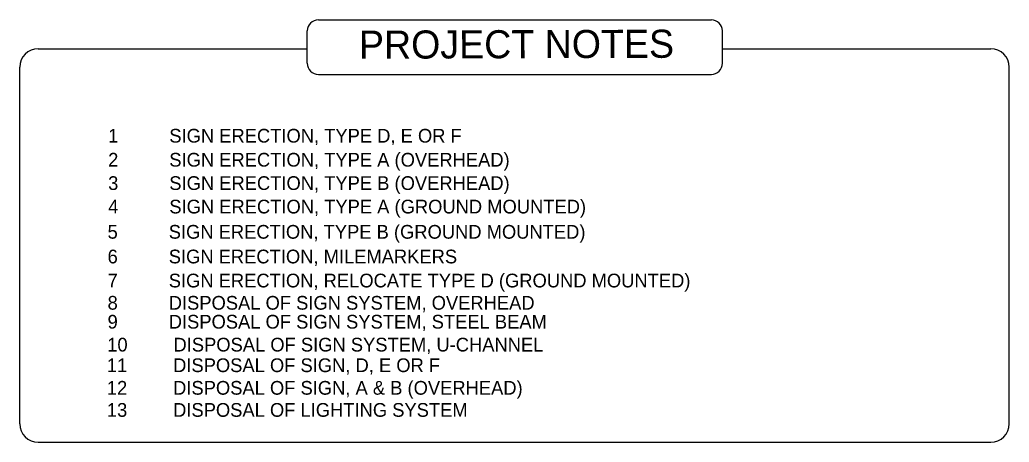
# Model space of a CAD drawing. Extents: x 49862 to 50351, y 49646 to 49855.
import ezdxf

# ---------------------------------------------------------------- set-up
doc = ezdxf.new("R2010")
doc.units = 0
doc.layers.add('Default', color=7, linetype='Continuous')
doc.layers.add('Sheet Title CELL', color=7, linetype='Continuous')

msp = doc.modelspace()

# ---------------------------------------------------------------- linework, layer by layer
at = {"layer": 'Sheet Title CELL'}
for p, q in [((50004.11, 49833.44), (50004.11, 49849.46)), ((50209.04, 49833.44), (50209.04, 49849.46)), ((49871.27, 49840.66), (50004.11, 49840.66)), ((50209.04, 49840.66), (50341.55, 49840.66)), ((49862.18, 49655.56), (49862.18, 49831.57)), ((50350.64, 49655.56), (50350.64, 49831.57)), ((49871.27, 49646.48), (50341.55, 49646.48))]:
    msp.add_line(p, q, dxfattribs=at)
for points in [[(50009.57, 49854.92), (50203.59, 49854.92)], [(50009.57, 49827.99), (50203.59, 49827.99)]]:
    msp.add_lwpolyline(points, dxfattribs=at)
for centre, radius, start, end in [((50009.57, 49849.46), 5.45, 90, 180), ((50203.59, 49849.46), 5.45, 0, 90), ((49871.27, 49831.57), 9.09, 90, 180), ((50341.55, 49831.57), 9.09, 0, 90), ((50009.57, 49833.44), 5.45, 180, 270), ((50203.59, 49833.44), 5.45, 270, 0), ((49871.27, 49655.56), 9.09, 180, 270), ((50341.55, 49655.56), 9.09, 270, 0)]:
    msp.add_arc(centre, radius, start, end, dxfattribs=at)

# ---------------------------------------------------------------- texts
at = {"layer": 'Default'}
msp.add_text('PROJECT NOTES', height=13.8661, rotation=0.1822, dxfattribs=at).set_placement((50029.63, 49835.69))
for s, p in [('1          SIGN ERECTION, TYPE D, E OR F', (49905.8, 49794.32)), ('2          SIGN ERECTION, TYPE A (OVERHEAD)', (49905.8, 49782.47)), ('3          SIGN ERECTION, TYPE B (OVERHEAD)', (49905.8, 49770.95)), ('4          SIGN ERECTION, TYPE A (GROUND MOUNTED)', (49905.8, 49759.35)), ('5          SIGN ERECTION, TYPE B (GROUND MOUNTED)', (49905.52, 49746.9)), ('6          SIGN ERECTION, MILEMARKERS', (49905.52, 49734.72)), ('7          SIGN ERECTION, RELOCATE TYPE D (GROUND MOUNTED)', (49905.52, 49722.86)), ('8          DISPOSAL OF SIGN SYSTEM, OVERHEAD', (49905.52, 49711.87)), ('9          DISPOSAL OF SIGN SYSTEM, STEEL BEAM', (49905.52, 49702.54)), ('10         DISPOSAL OF SIGN SYSTEM, U-CHANNEL', (49905.34, 49691.23)), ('11         DISPOSAL OF SIGN, D, E OR F', (49905.16, 49681.07)), ('12         DISPOSAL OF SIGN, A & B (OVERHEAD)', (49905.16, 49669.92)), ('13         DISPOSAL OF LIGHTING SYSTEM', (49905.16, 49659.01))]:
    msp.add_text(s, height=6.7709, dxfattribs=at).set_placement(p)

doc.saveas('drawing.dxf')
